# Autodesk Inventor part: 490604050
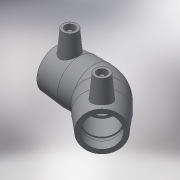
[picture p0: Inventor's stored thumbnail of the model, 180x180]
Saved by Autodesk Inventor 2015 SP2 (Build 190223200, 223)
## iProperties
Created: 2017-06
Part Number: 490604050
Material: Generic
Description: PLASSON 45° ELBOW 50
Document SubType Name: Modeling
Designer: KIM
Mass: 55.0731 g
Surface Area: 148.067 cm^2
Volume: 55.0731 cm^3
Density: 1 g/cm^3
Appearance: Default
Author: KIM
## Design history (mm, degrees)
derived "490604.ipt"
feature "Solid1::490604.ipt"
tag "TaggingFeature1"
body "Solid1"
other parameters: "d2" = 68, "d4" = 31.25, "d5" = 61.2, "d8" = 168 deg, "d10" = 19.6, "d11" = 6.53333, "d14" = 17.6296, "d19" = 3.52592, "d20" = 168 deg, "d22" = 62.56, "d23" = 68, "d24" = 60.6832, "d29" = 51, "d30" = 15, "d31" = 43.75, "d34" = 5 deg, "d35" = 12, "d39" = 0, "d41" = 4, "d42" = 14, "d43" = 0, "d44" = 9.6, "d45" = 4.8, "d46" = 6, "d47" = 0, "d50" = 42.5, "d51" = 19.6, "d52" = 49, "d54" = 135 deg, "d67" = 45 deg, "d71" = 135 deg, "d75" = 3.4, "d82" = 45 deg, "d83" = 49, "d84" = 61.2, "d86" = 30.6, "d87" = 135 deg, "d88" = 125, "d90" = 49, "d91" = 0, "d92" = 49, "d93" = 0, "d94" = 135 deg, "d95" = 31.28, "d98" = 125, "d99" = 37.5, "d101" = 3, "d102" = 0, "d103" = 3, "d104" = 0, "d105" = 14.21, "d106" = 3.5525, "L_" = 125, "L_1" = 49, "D_" = 68, "A_" = 51, "d_2" = 12
